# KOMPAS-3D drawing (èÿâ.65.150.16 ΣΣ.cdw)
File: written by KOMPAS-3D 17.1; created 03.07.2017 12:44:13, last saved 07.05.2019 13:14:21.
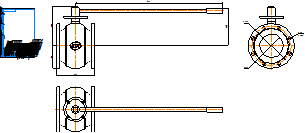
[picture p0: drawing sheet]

Sheet 1: A4, portrait

Title block, sheet 1: name: КШГ.65.150.16 фф; material: Внимание! Данный продукт является объектом авторского права ООО «Торговый Дом АДЛ». / Запрещается изменение, копирование, распространение / (в том числе путем копирования на другие сайты и ресурсы в Интернете) / или любое иное использование информации и объектов без предварительного / согласия правообладателя (ООО «Торговый Дом АДЛ»).; sheets: 1; organisation: ООО "Торговый дом АДЛ"; sheet format: A4; stored path: C:\Users\kka\KOMPAS_Work\!Trash\СС02 СС03 ФФ Смотровые стекла\СС01.cdw

Views: Спереди 1, Проекционный вид 2, Проекционный вид 3
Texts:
  Klimkovich
  ADL
Dimensions and other numbers on the sheet: 900; 229; 236; 140; 243; 240; 146; 22; 8 Отв.; 1:1; 1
